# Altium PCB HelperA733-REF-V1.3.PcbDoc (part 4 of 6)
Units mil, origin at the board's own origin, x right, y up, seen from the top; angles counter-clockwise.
Board outline 5905.51 x 4133.86 mil, 2 copper layers (Top, Bottom), stack 12.7 mil thick; 446 components, 341 nets, 1706 pads, 1667 vias.
Unrouted connection lines stored in the file: 1382.
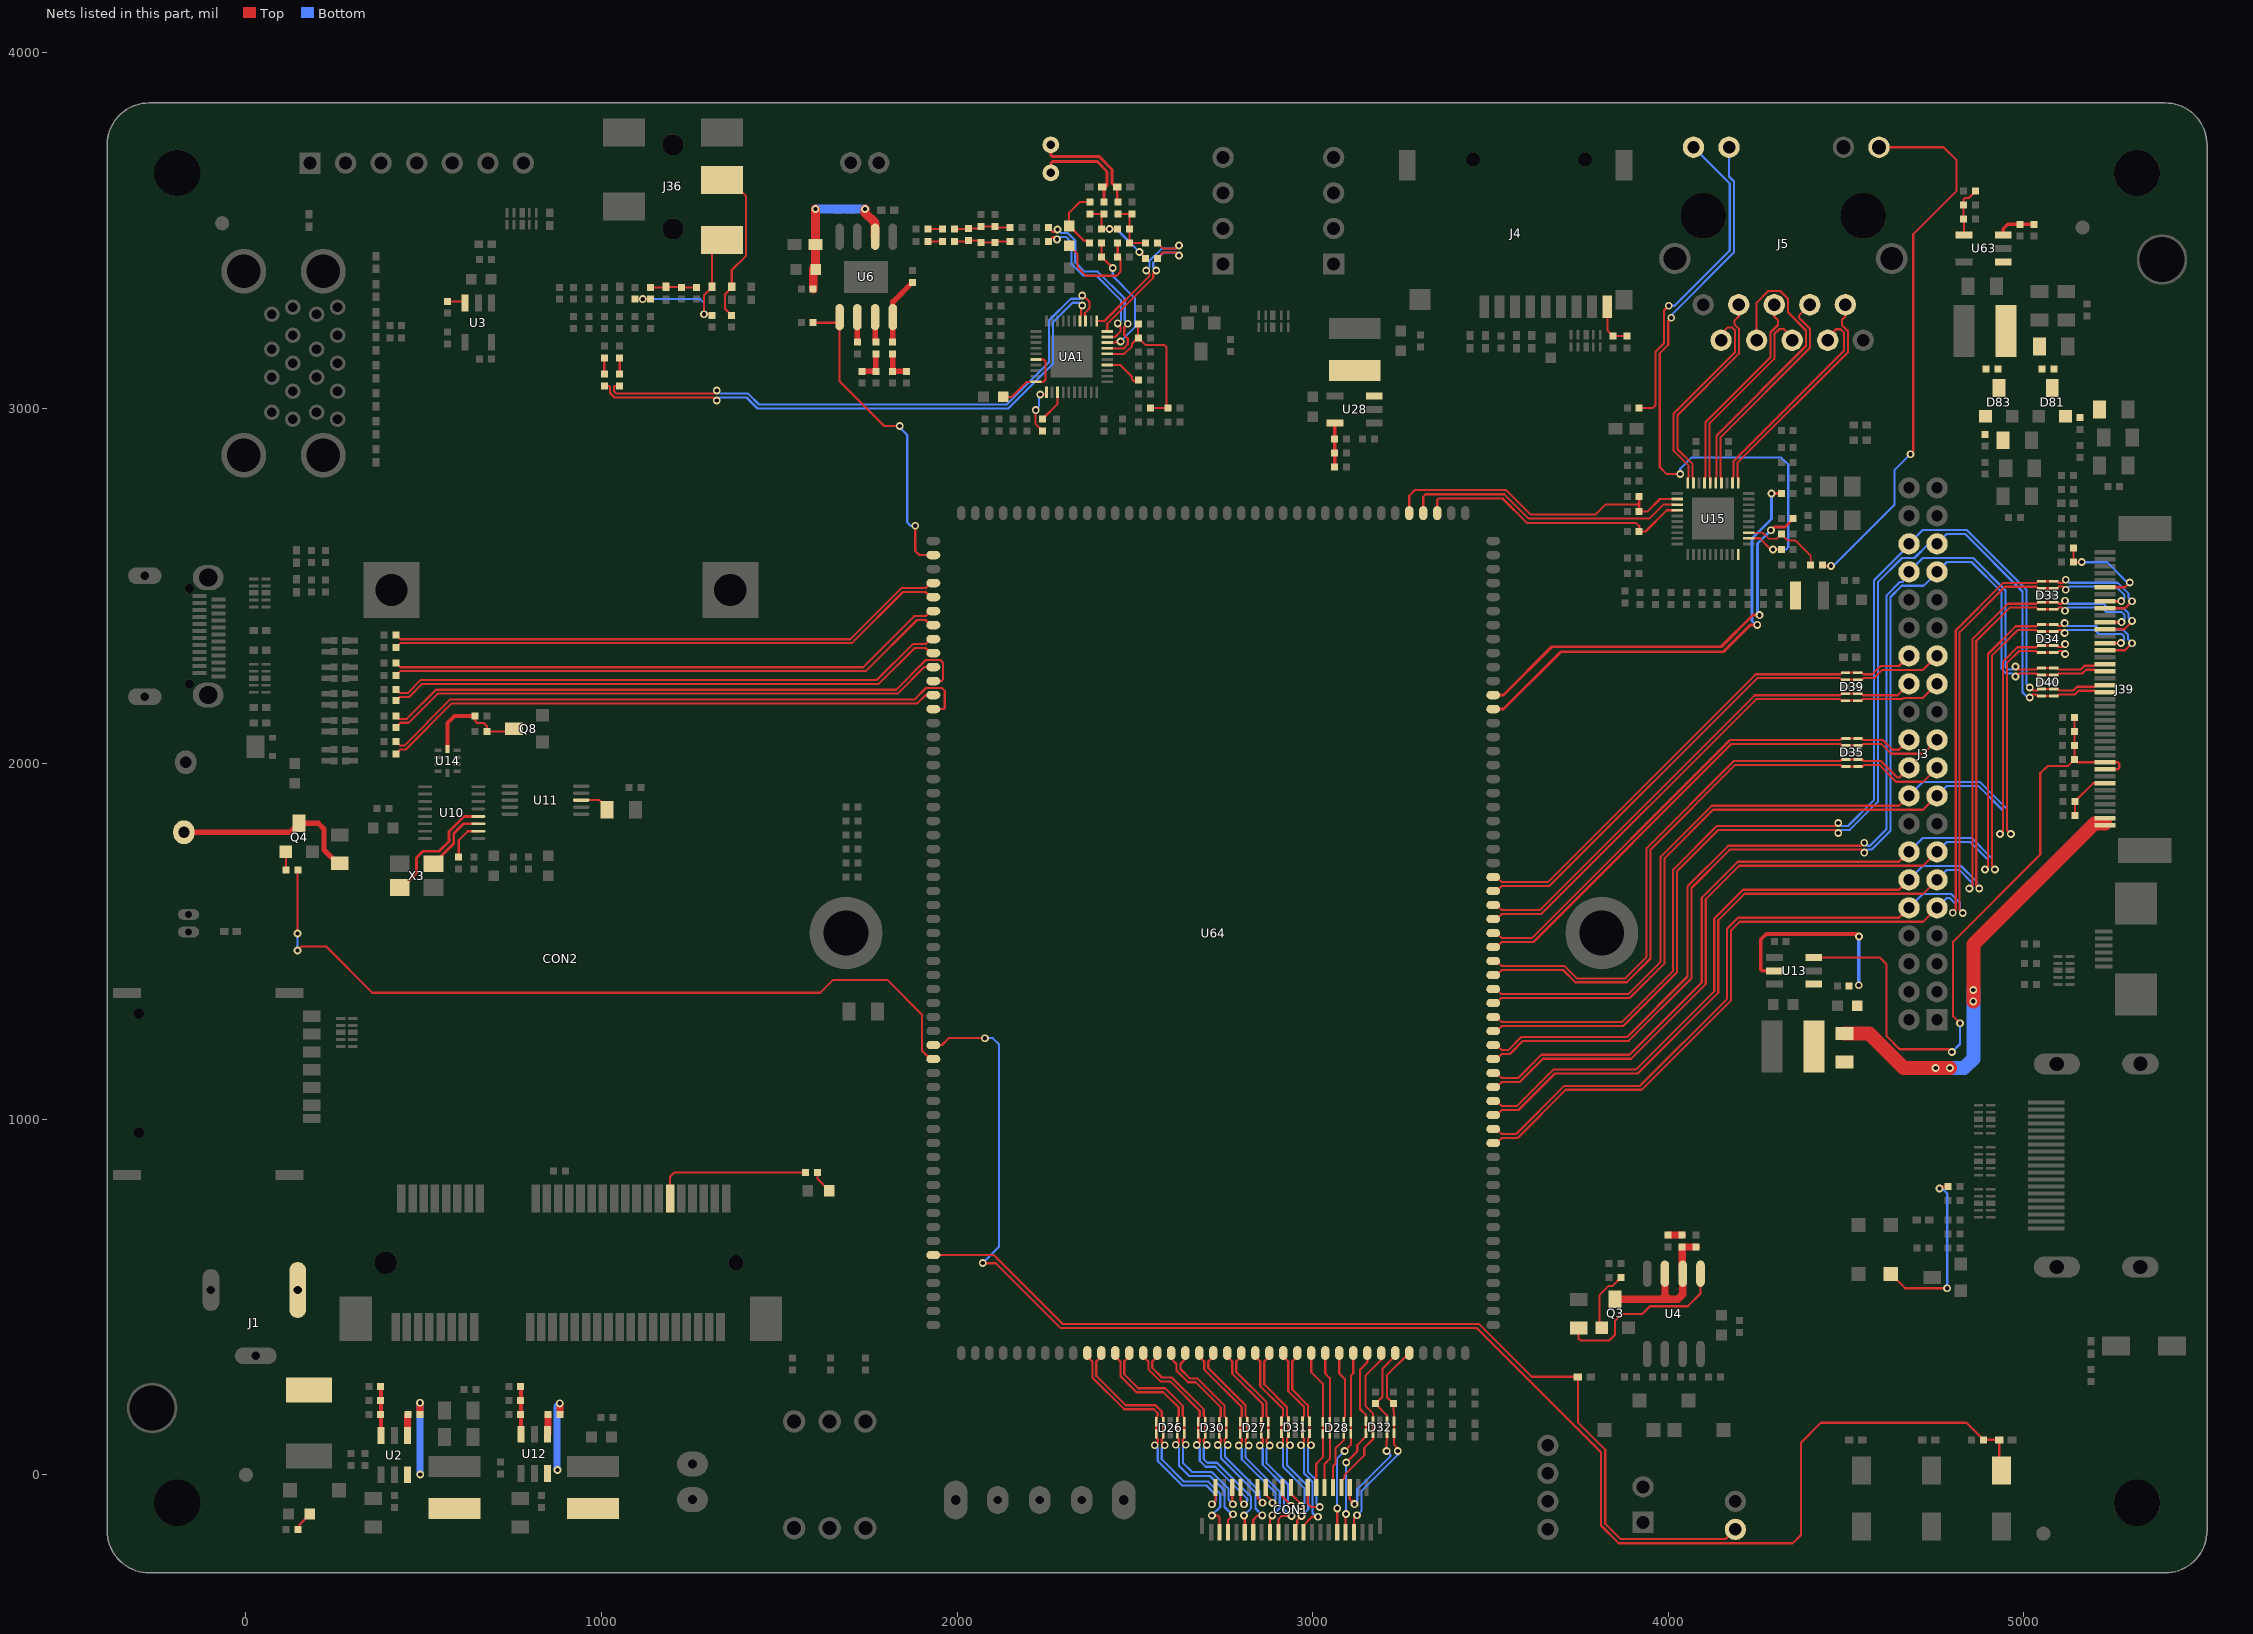
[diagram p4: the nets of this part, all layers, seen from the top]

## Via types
v1: diameter 22, hole 12, Top to Bottom, 1667 vias

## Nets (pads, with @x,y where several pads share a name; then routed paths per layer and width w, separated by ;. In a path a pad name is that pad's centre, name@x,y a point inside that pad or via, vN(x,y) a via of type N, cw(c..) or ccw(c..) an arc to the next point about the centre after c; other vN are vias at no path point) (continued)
LCD_UD: J39.34 R202.2 R204.1 | length 145.2
  Top w6: R202.2@5143.7,1854.33 R204.1@5143.7,1893.7 5194.88,1944.88 J39.34@5228.35,1944.88
LDOIN/RSTN: CA17.1 RA17.1 RA18.2 RA20.1 UA1.36 | length 469.1
  Top w6: UA1.36@2422.44,3152.58 2470.44,3152.58 2492.15,3174.29 2492.15,3181.72 CA17.1@2508.89,3198.45 ; RA18.2@2510.83,3236.22 2508.89,3234.28 CA17.1@2508.89,3198.45 ; RA17.1@2544.29,3000 RA20.1@2593.5,3000 ; RA20.1@2599.6,3000 RA20.1@2593.5,3000 ; CA17.1@2508.89,3198.45 2508.89,3196.85 CA17.1@2510.83,3196.85 2530.51,3177.17 2583.06,3177.17 2588.45,3171.78 2588.45,3005.05 RA20.1@2593.5,3000
LED0_AD0: J5.13 R149.2 U15.32 | length 1780.4
  Top w6: v1(4008.45,3253.89) 4000.2,3245.64 4000.2,3177.93 3976.1,3153.83 3976.1,2834.12 3995.87,2814.35 v1(4033.65,2814.35) ; U15.32@4226.38,2633.86 4257.27,2633.86 4288.76,2602.36 v1(4294.35,2602.36) R149.2@4317.91,2602.36
  Bottom w6: v1(4008.45,3253.89) 4008.45,3261.33 4185.09,3437.97 4185.09,3637.21 4171.05,3651.25 J5.13@4171.05,3733.64 ; v1(4033.65,2814.35) 4033.65,2829.3 4065.08,2860.73 4318.1,2860.73 4337.48,2841.35 4337.48,2608.83 4331.01,2602.36 v1(4294.35,2602.36)
LED1_AD1: R79.2 R150.2 U15.33 | length 237.8
  Top w5: U15.33@4226.38,2649.61 4266.22,2649.61 4283.38,2632.45 4304.69,2632.45 R150.2@4317.91,2645.67 4336.27,2627.31 4358.14,2627.31 4400.59,2584.86 R79.2@4400.59,2559.06
LED+: C91.1 C215.1 D46.2 J39.39 J39.40 U13.5 | length 1865.3
  Top w10: U13.5@4299.21,1417.32 4264.43,1417.32 4260.65,1421.1 4260.65,1505.67 4275.94,1520.96 4529.7,1520.96 v1(4536.6,1514.05)
  Top w39.37: v1(4857.86,1331.56) v1(4857.86,1363.56) 4857.86,1490.84 5199.26,1832.24 J39.40@5228.35,1832.24
  Top w40: D46.2@4496.06,1240.79 4565.31,1240.79 4662.1,1144 v1(4752,1144) v1(4792,1144)
  Bottom w10: v1(4535.8,1376.91) 4535.8,1514.05 v1(4536.6,1514.05)
  Bottom w39.37: v1(4752,1144) v1(4792,1144) 4832,1144 4857.86,1169.86 v1(4857.86,1331.56) v1(4857.86,1363.56)
LED-: J39.31 J39.32 R6.1 R216.1 R217.1 R218.1 U13.3 | length 1934.8
  Top w6: U13.3@4409.45,1454.72 4594.63,1454.72 4614.05,1435.3 4614.05,1233.06 4650.2,1196.91 4789.47,1196.91 v1(4797.59,1188.79) ; v1(4820.54,1269.96) 4801.08,1289.42 4801.08,1499.22 5046.36,1744.5 5046.36,1972.89 5066.43,1992.96 5123.87,1992.96 R218.1@5142.72,2011.81 ; R217.1@5142.72,2129.92 R216.1@5142.72,2090.55 R6.1@5142.72,2051.18 R218.1@5142.72,2011.81 ; J39.32@5228.35,1984.25 5265.03,1984.25 5268.22,1987.44 5268.22,2000.08 5264.36,2003.94 5150.59,2003.94 R218.1@5142.72,2011.81
  Bottom w6: v1(4797.59,1188.79) 4820.54,1211.74 v1(4820.54,1269.96)
LRADC0: D172.2 J42.1 U64.183 | length 2796.7
  Top w6: U64.183@1933.07,618.11 2102.77,618.11 2296.27,424.61 3467.2,424.61 3616.22,275.59 D172.2@3745.78,275.59 ; D172.2@3747.78,275.59 D172.2@3745.78,275.59 ; J42.1@4188.98,-153.54 4162.25,-180.27 3865.31,-180.27 3822.83,-137.8 3822.83,70.91 3745.78,147.96 D172.2@3745.78,275.59
LVDS0-CKN: D40.1 D40.10 J3.34 J39.17 U64.58 | length 3119.8
  Top w6: U64.58@3507.87,1208.66 3517.71,1208.66 3531.9,1194.47 3550.07,1194.47 3586.94,1231.34 3884.28,1231.34 4054.2,1401.26 4054.2,1655.14 4168.31,1769.24 4542.87,1769.24 v1(4551.37,1777.74) ; v1(4976.37,2273.16) 4984.86,2264.66 5034.94,2264.66 5039.28,2269.01 D40.10@5083.97,2269.01 5093.83,2269.01 5098.17,2264.66 5160.16,2264.66 5170.68,2275.18 5197.1,2275.18 5201.44,2279.53 J39.17@5228.35,2279.53
  Bottom w6: v1(4551.37,1777.74) 4559.87,1769.24 4567.21,1769.24 4614.09,1816.12 4614.09,2473.42 4651.88,2511.21 4659.5,2511.21 4677.17,2528.87 J3.34@4677.17,2539.37 4716.17,2578.37 4857.51,2578.37 4948.7,2487.18 4948.7,2271.17 4955.21,2264.66 4967.87,2264.66 v1(4976.37,2273.16)
LVDS0-CKP: D40.2 D40.9 J3.33 J39.18 U64.57 | length 3114.3
  Top w6: U64.57@3507.87,1169.29 3517.71,1169.29 3531.9,1183.47 3554.77,1183.47 3591.63,1220.34 3888.86,1220.34 4065.27,1396.75 4065.27,1650.45 4173.07,1758.24 4542.87,1758.24 v1(4551.37,1749.74) ; v1(4976.37,2245.16) 4984.87,2253.66 5034.91,2253.66 5039.25,2249.32 D40.9@5083.97,2249.32 5094.25,2249.32 5098.59,2253.66 5164.72,2253.66 5175.24,2264.19 5197.61,2264.19 5201.95,2259.84 J39.18@5228.35,2259.84
  Bottom w6: v1(4551.37,1749.74) 4559.87,1758.24 4571.77,1758.24 4625.09,1811.56 4625.09,2468.85 4656.44,2500.2 4718.39,2500.2 4755.91,2537.72 J3.33@4755.91,2539.37 4783.86,2567.32 4852.73,2567.32 4937.67,2482.39 4937.67,2266.6 4950.61,2253.66 4967.87,2253.66 v1(4976.37,2245.16)
LVDS0-D0N: D33.2 D33.9 J3.10 J39.8 U64.52 | length 3154
  Top w6: U64.52@3507.87,972.44 3517.71,972.44 3531.9,958.25 3571.77,958.25 3707.31,1093.79 3920.53,1093.79 4165.77,1339.03 4165.77,1536.22 4196.07,1566.52 4649.19,1566.52 J3.10@4677.17,1594.49 ; v1(4828.16,1580.14) 4819.42,1588.88 4819.42,2369.62 4947.16,2497.36 5035.6,2497.36 5039.55,2493.41 D33.9@5083.97,2493.41 5094.08,2493.41 5098.43,2497.76 5109.58,2497.76 v1(5118.08,2489.26) ; J39.8@5228.35,2456.69 5274.79,2456.69 5274.79,2457.04 v1(5274.22,2457.04)
  Bottom w6: J3.10@4677.17,1594.49 4716.17,1633.49 4795.6,1633.49 4820.03,1609.05 4820.03,1588.27 v1(4828.16,1580.14) ; v1(5118.08,2489.26) 5126.58,2497.76 5259.28,2497.76 5283.63,2473.41 5283.63,2466.45 v1(5274.22,2457.04)
LVDS0-D0P: D33.1 D33.10 J3.9 J39.9 U64.51 | length 3209.1
  Top w6: U64.51@3507.87,933.07 3517.71,933.07 3531.9,947.25 3576.33,947.25 3711.87,1082.79 3925.12,1082.79 4176.89,1334.57 4176.89,1531.6 4200.78,1555.49 4716.91,1555.49 J3.9@4755.91,1594.49 ; v1(4799.94,1580.49) 4808.42,1588.97 4808.42,2374.36 4942.42,2508.36 5035.6,2508.36 5040.34,2513.1 D33.10@5083.97,2513.1 5093.73,2513.1 5098.08,2508.76 5109.58,2508.76 v1(5118.08,2517.26) ; J39.9@5228.35,2437.01 5284.45,2437.01 v1(5304.13,2456.69)
  Bottom w6: J3.9@4755.91,1594.49 4783.91,1622.49 4790.95,1622.49 4809,1604.43 4809,1589.55 v1(4799.94,1580.49) ; v1(5118.08,2517.26) 5126.58,2508.76 5263.88,2508.76 5294.65,2477.99 5294.65,2466.18 v1(5304.13,2456.69)
LVDS0-D1N: D33.5 D33.6 J3.12 J39.11 U64.54 | length 3050.1
  Top w6: U64.54@3507.87,1051.18 3517.71,1051.18 3531.9,1036.99 3574.32,1036.99 3676.83,1139.5 3909.06,1139.5 4129.47,1359.92 4129.47,1564.31 4210.39,1645.23 4649.17,1645.23 J3.12@4677.17,1673.23 ; v1(4874.85,1649.16) 4866.35,1657.66 4866.35,2345.06 4960,2438.7 5035.59,2438.7 5039.93,2434.36 D33.6@5083.97,2434.36 5093.91,2434.36 5098.25,2438.7 5107.34,2438.7 v1(5115.84,2430.2) ; J39.11@5228.35,2397.64 5274.59,2397.64 v1(5274.59,2398)
  Bottom w6: J3.12@4677.17,1673.23 4716.17,1712.23 4823.25,1712.23 4866.35,1669.12 4866.35,1657.66 v1(4874.85,1649.16) ; v1(5115.84,2430.2) 5124.34,2438.7 5219.7,2438.7 5232.36,2426.04 5275.89,2426.04 5283.41,2418.52 5283.41,2406.81 v1(5274.59,2398)
LVDS0-D1P: D33.4 D33.7 J3.11 J39.12 U64.53 | length 3105.7
  Top w6: U64.53@3507.87,1011.81 3517.71,1011.81 3531.9,1025.99 3578.87,1025.99 3681.38,1128.5 3913.78,1128.5 4140.54,1355.26 4140.54,1559.69 4215.08,1634.23 4716.91,1634.23 J3.11@4755.91,1673.23 ; v1(4846.85,1649.16) 4855.35,1657.66 4855.35,2349.99 4955.06,2449.7 5035.17,2449.7 5039.51,2454.04 D33.7@5083.97,2454.04 5094.52,2454.04 5098.87,2449.7 5107.34,2449.7 v1(5115.84,2458.2) ; J39.12@5228.35,2377.95 5282.83,2377.95 5304.13,2399.25 v1(5304.13,2401.57)
  Bottom w6: J3.11@4755.91,1673.23 4783.84,1701.16 4818.69,1701.16 4855.35,1664.5 4855.35,1657.66 v1(4846.85,1649.16) ; v1(5115.84,2458.2) 5124.34,2449.7 5224.26,2449.7 5236.92,2437.04 5280.47,2437.04 5294.46,2423.05 5294.46,2411.25 v1(5304.13,2401.57)
LVDS0-D2N: D34.2 D34.9 J3.14 J39.14 U64.56 | length 2984.1
  Top w6: U64.56@3507.87,1129.92 3517.71,1129.92 3531.9,1115.73 3577.6,1115.73 3643.08,1181.21 3891.16,1181.21 4094.42,1384.48 4094.42,1623.15 4195.24,1723.97 4649.17,1723.97 J3.14@4677.17,1751.97 ; 4910.1,1770.25 4910.1,2303.49 4982.23,2375.62 5035.03,2375.62 5039.28,2371.37 D34.9@5083.97,2371.37 5086.82,2371.37 5094.07,2371.37 5098.42,2375.71 5106.29,2375.71 v1(5114.79,2367.21) ; 4910.1,1770.24 4910.1,1710.71 v1(4918.6,1702.21) ; J39.14@5228.35,2338.58 5275.73,2338.58 v1(5272.89,2339.15)
  Bottom w6: J3.14@4677.17,1751.97 4716.17,1790.97 4853.24,1790.97 4910.1,1734.11 4910.1,1710.71 v1(4918.6,1702.21) ; v1(5114.79,2367.21) 5123.29,2375.71 5199.14,2375.71 5210.43,2364.42 5275.9,2364.42 5281.94,2358.39 5281.94,2348.19 v1(5272.89,2339.15)
LVDS0-D2P: D34.1 D34.10 J3.13 J39.15 U64.55 | length 3037.6
  Top w6: U64.55@3507.87,1090.55 3517.71,1090.55 3531.9,1104.73 3582.16,1104.73 3647.63,1170.21 3895.75,1170.21 4105.5,1379.96 4105.5,1618.63 4199.83,1712.97 4716.91,1712.97 J3.13@4755.91,1751.97 ; v1(4890.6,1702.21) 4899.1,1710.71 4899.1,1765.69 ; 4899.1,1765.69 4899.1,2308.29 4977.43,2386.62 5035.75,2386.62 5040.18,2391.06 D34.10@5083.97,2391.06 5093.16,2391.06 5097.51,2386.71 5106.29,2386.71 v1(5114.79,2395.21) ; J39.15@5228.35,2318.9 5284.45,2318.9 v1(5304.13,2338.58)
  Bottom w6: J3.13@4755.91,1751.97 4783.91,1779.97 4848.5,1779.97 4899.1,1729.37 4899.1,1710.71 v1(4890.6,1702.21) ; v1(5114.79,2395.21) 5123.29,2386.71 5203.7,2386.71 5214.99,2375.42 5280.46,2375.42 5292.95,2362.93 5292.95,2349.77 v1(5304.13,2338.58)
LVDS0-D3N: D40.4 D40.7 J3.36 J39.20 U64.60 | length 3189.5
  Top w6: U64.60@3507.87,1287.4 3517.71,1287.4 3531.9,1273.21 3869.3,1273.21 4013.74,1417.65 4013.74,1701.8 4136.61,1824.67 4469.53,1824.67 v1(4478.03,1833.17) ; v1(5016.94,2214.11) 5025.44,2205.61 5036.12,2205.61 5040.46,2209.95 D40.7@5083.97,2209.95 5094.96,2209.95 5099.3,2205.61 5139.13,2205.61 5149.65,2216.13 5198.6,2216.13 5202.94,2220.47 J39.20@5228.35,2220.47
  Bottom w6: v1(4478.03,1833.17) 4486.53,1824.67 4505.64,1824.67 4578.28,1897.31 4578.28,2515.02 4677.17,2613.9 J3.36@4677.17,2618.11 4716.17,2657.11 4839.06,2657.11 5007.51,2488.66 5007.51,2223.54 v1(5016.94,2214.11)
LVDS0-D3P: D40.5 D40.6 J3.35 J39.21 U64.59 | length 3204.9
  Top w6: U64.59@3507.87,1248.03 3517.71,1248.03 3531.9,1262.21 3873.92,1262.21 4024.78,1413.07 4024.78,1697.21 4141.24,1813.67 4469.53,1813.67 v1(4478.03,1805.17) ; v1(5016.94,2186.11) 5025.44,2194.61 5034.18,2194.61 5038.52,2190.27 D40.6@5083.97,2190.27 5093.75,2190.27 5098.09,2194.61 5143.69,2194.61 5154.21,2205.13 5198.21,2205.13 5202.55,2200.79 J39.21@5228.35,2200.79
  Bottom w6: v1(4478.03,1805.17) 4486.53,1813.67 4510.32,1813.67 4589.41,1892.76 4589.41,2510.53 4657.29,2578.41 4692.69,2578.41 4732.39,2618.11 J3.35@4755.91,2618.11 4783.91,2646.11 4834.5,2646.11 4996.38,2484.24 4996.38,2200.67 5010.94,2186.11 v1(5016.94,2186.11)
LVDS1-CKN: D39.2 D39.9 J3.26 U64.68 | length 1442.3
  Top w6: U64.68@3507.87,1602.36 3517.71,1602.36 3531.9,1588.18 3638.51,1588.18 4242.85,2192.51 4482.88,2192.51 4487.22,2196.86 D39.2@4532.79,2196.86 4543.15,2196.86 4547.49,2192.51 4645.27,2192.51 J3.26@4677.17,2224.41
LVDS1-CKP: D39.1 D39.10 J3.25 U64.67 | length 1525.6
  Top w6: U64.67@3507.87,1562.99 3517.71,1562.99 3531.9,1577.18 3643.07,1577.18 4247.41,2181.51 4482.44,2181.51 4486.78,2177.17 D39.1@4532.79,2177.17 4542.9,2177.17 4547.24,2181.51 4657.85,2181.51 4661.01,2184.67 4716.17,2184.67 J3.25@4755.91,2224.41
LVDS1-D0N: D34.5 D34.6 J3.18 U64.62 | length 2647.7
  Top w6: U64.62@3507.87,1366.14 3515.75,1366.14 3529.93,1351.95 3887.48,1351.95 3978.75,1443.22 3978.75,1738.5 4121.92,1881.67 4649.38,1881.67 J3.18@4677.17,1909.45 ; v1(4963.57,1802.25) 4952.33,1813.48 4952.33,2282.33 4986.47,2316.47 5034.1,2316.47 5038.25,2312.32 D34.6@5083.97,2312.32 5085.75,2312.32 5093.74,2312.32 5098.09,2316.66 5107.68,2316.66 v1(5116.18,2308.16)
  Bottom w6: J3.18@4677.17,1909.45 4716.17,1948.45 4715.79,1948.83 4876.24,1948.83 4952.33,1872.74 4952.33,1815.18 4963.57,1803.94 v1(4963.57,1802.25)
LVDS1-D0P: D34.4 D34.7 J3.17 U64.61 | length 2644.6
  Top w6: U64.61@3507.87,1326.77 3515.75,1326.77 3529.93,1340.95 3892.04,1340.95 3989.75,1438.67 3989.75,1733.94 4126.02,1870.21 4716.67,1870.21 J3.17@4755.91,1909.45 ; v1(4932.81,1802.18) 4941.33,1810.7 4941.33,2286.89 4981.91,2327.47 5035.43,2327.47 5039.96,2332 D34.7@5083.97,2332 5086.01,2332 5092.99,2332 5097.33,2327.66 5107.68,2327.66 v1(5116.18,2336.16)
  Bottom w6: J3.17@4755.91,1909.45 4783.91,1937.45 4871.94,1937.45 4941.33,1868.06 4941.33,1810.7 v1(4932.81,1802.18)
LVDS1-D1N: D35.2 D35.9 J3.20 U64.64 | length 1656
  Top w6: U64.64@3507.87,1444.88 3517.71,1444.88 3531.9,1430.69 3708.52,1430.69 3742.95,1396.27 3878.94,1396.27 3939.15,1456.49 3939.15,1762.54 4184.08,2007.47 4483.45,2007.47 4487.79,2011.82 D35.9@4499.69,2011.82 D35.2@4533.77,2011.82 4545.36,2011.82 4549.7,2007.47 4597.92,2007.47 4644.43,1960.96 4649.94,1960.96 J3.20@4677.17,1988.19
LVDS1-D1P: D35.1 D35.10 J3.19 U64.63 | length 1739.9
  Top w6: U64.63@3507.87,1405.51 3517.71,1405.51 3531.9,1419.69 3703.97,1419.69 3738.39,1385.27 3883.51,1385.27 3950.17,1451.93 3950.17,1757.95 4188.69,1996.47 4484.47,1996.47 4488.81,1992.13 D35.10@4499.69,1992.13 D35.1@4533.77,1992.13 4546.43,1992.13 4550.77,1996.47 4593.36,1996.47 4640.64,1949.19 4716.91,1949.19 J3.19@4755.91,1988.19
LVDS1-D2N: D35.5 D35.6 J3.22 U64.66 | length 1432.5
  Top w6: U64.66@3507.87,1523.62 3517.71,1523.62 3531.9,1509.43 3616.39,1509.43 4173.48,2066.53 4484.11,2066.53 4488.45,2070.87 D35.6@4499.69,2070.87 D35.5@4533.77,2070.87 4544.33,2070.87 4548.67,2066.53 4603.69,2066.53 4631.28,2038.94 4649.18,2038.94 J3.22@4677.17,2066.93
LVDS1-D2P: D35.4 D35.7 J3.21 U64.65 | length 1515.8
  Top w6: U64.65@3507.87,1484.25 3517.71,1484.25 3531.9,1498.44 3620.95,1498.44 4178.04,2055.53 4483.55,2055.53 4487.89,2051.19 D35.7@4499.69,2051.19 D35.4@4533.77,2051.19 4544.19,2051.19 4548.53,2055.53 4599.14,2055.53 4626.73,2027.93 4716.91,2027.93 J3.21@4755.91,2066.93
LVDS1-D3N: D39.5 D39.6 J3.28 U64.70 | length 1442.3
  Top w6: U64.70@3507.87,1681.1 3517.71,1681.1 3531.9,1666.92 3661.05,1666.92 4245.7,2251.57 4484.01,2251.57 4488.35,2255.91 4544.7,2255.91 4549.04,2251.57 4573.96,2251.57 4597.17,2274.78 4648.8,2274.78 J3.28@4677.17,2303.15
LVDS1-D3P: D39.4 D39.7 J3.27 U64.69 | length 1525.6
  Top w6: U64.69@3507.87,1641.73 3517.71,1641.73 3531.9,1655.92 3665.63,1655.92 4250.28,2240.57 4482.83,2240.57 4487.17,2236.23 4545.08,2236.23 4549.42,2240.57 4578.51,2240.57 4601.73,2263.78 4716.54,2263.78 J3.27@4755.91,2303.15
MBIAS: CA5.2 RA5.2 UA1.38 | length 371.1
  Top w6: RA5.2@2406.5,3464.57 CA5.2@2406.5,3425.2 2406.68,3425.2 2426.01,3405.86 2426.21,3405.86 2427.93,3405.35 v1(2437.81,3393.66) ; UA1.38@2422.44,3184.08 2451.91,3184.04 2451.91,3184.21 v1(2459.96,3187.57)
  Bottom w6: v1(2437.81,3393.66) 2437.81,3371.39 2500.05,3309.15 2500.05,3227.67 v1(2459.96,3187.57)
MCSI0-MCLK: CON1.26 D28.1 D28.10 U64.26 | length 399.1
  Top w6: U64.26@2996.06,342.52 2996.06,288.48 3028.57,255.97 D28.1@3028.57,115.28 3028.57,49.78 3009.97,31.18 CON1.26@3009.97,-35.4
MCSI2-MCLK: CON1.28 D28.2 D28.9 U64.27 | length 389.3
  Top w6: CON1.28@3033.59,-35.4 3033.59,30.5 3048.26,45.17 D28.2@3048.26,115.28 3048.26,271.99 3035.43,284.82 U64.27@3035.43,342.52
MCSI-RST-F: CON1.31 D28.5 D28.6 U64.29 | length 522.7
  Top w6: v1(3068.92,-94.38) 3069.02,-94.49 CON1.31@3069.02,-161.38 ; v1(3089.92,67.15) 3107.31,84.54 D28.5@3107.31,115.28 3107.31,278.58 3114.17,285.44 U64.29@3114.17,342.52
  Bottom w6: v1(3068.92,-94.38) 3068.92,46.15 v1(3089.92,67.15)
MCSI-RST-R: CON1.32 D32.4 D32.7 U64.31 | length 441.6
  Top w6: CON1.32@3080.83,-35.4 3080.83,-17.68 3089.2,-9.31 3089.2,-0.87 3145.04,54.97 3145.04,75.75 3164,94.71 3164.72,94.71 3169.29,99.27 D32.7@3169.29,116.82 D32.4@3169.29,150.9 3169.29,172.82 3148.98,193.13 3148.98,279.75 3192.91,323.68 U64.31@3192.91,342.52
MCSI-SCK-TWI2: CON1.34 D32.2 D32.9 R8.2 U64.32 | length 572.9
  Top w6: CON1.34@3104.45,-35.4 3104.45,-69.5 3108.8,-73.85 3112.14,-72.8 v1(3117.48,-82.46) v1@3110.67,-74.27 ; v1(3208.03,67.15) 3208.03,94.08 3208.66,94.71 D32.9@3208.66,116.82 D32.2@3208.66,150.9 3208.66,167.9 R8.2@3176.54,200.02 3196.64,220.13 3196.64,299.01 3232.28,334.65 U64.32@3232.28,342.52
  Bottom w6: v1(3117.48,-82.46) 3125.46,-74.48 3125.46,-40.49 3218.1,52.15 3218.1,57.08 v1(3208.03,67.15)
MCSI-SDA-TWI2: CON1.35 D32.1 D32.10 R9.2 U64.33 | length 593.8
  Top w6: CON1.35@3116.26,-161.38 3116.26,-122.48 v1(3124.88,-113.86) ; v1(3239.53,67.15) 3239.53,75.02 3228.35,86.2 D32.10@3228.35,116.82 D32.1@3228.35,150.9 3228.35,176.77 3227.72,177.4 R9.2@3227.72,200.02 3208.75,218.99 3208.75,279.61 U64.33@3271.65,342.52
  Bottom w6: v1(3124.88,-113.86) 3137.67,-101.07 3137.67,-45.28 3239.53,56.58 v1(3239.53,67.15)
MCSI-STBY-F: CON1.30 D28.4 D28.7 U64.28 | length 398.9
  Top w6: CON1.30@3057.21,-35.4 3057.21,23.61 3063.9,30.3 3063.9,73.92 3087.63,97.65 D28.4@3087.63,115.28 3087.63,160.39 3091.37,164.13 3091.37,268.23 3074.8,284.8 U64.28@3074.8,342.52
MCSI-STBY-R: CON1.33 D32.5 D32.6 U64.30 | length 543.6
  Top w6: CON1.33@3092.64,-161.38 3092.64,-111.23 v1(3093.86,-110.02) ; v1(3094.7,34.74) 3125.35,65.39 3125.35,83.41 3149.61,107.66 D32.6@3149.61,116.82 D32.5@3149.61,150.9 3149.61,168.81 3133.23,185.19 3133.23,295.5 3153.54,315.81 U64.30@3153.54,342.52
  Bottom w6: v1(3093.86,-110.02) 3093.86,31.72 3092.77,32.81 v1(3094.7,34.74)
MCSIA-CKN: CON1.14 D27.1 D27.10 U64.18 | length 580.3
  Top w6: U64.18@2681.1,342.52 2681.1,332.68 2695.29,318.49 2695.29,295.92 2800.63,190.58 2800.63,164.3 2796.28,159.96 D27.1@2796.28,115.28 2796.28,104.59 2800.61,100.27 2800.61,91 v1(2792.13,82.52) ; CON1.14@2868.23,-35.4 2868.23,-56.11 2889.09,-76.98 2890.69,-78.58 v1(2887.24,-78.83)
  Bottom w6: v1(2792.13,82.52) 2800.63,74.02 2800.63,43.84 2895.73,-51.27 2895.73,-70.34 v1(2887.24,-78.83)
MCSIA-CKP: CON1.15 D27.2 D27.9 U64.19 | length 619.4
  Top w6: U64.19@2720.47,342.52 2720.47,332.68 2706.29,318.49 2706.29,300.48 2811.63,195.14 2811.63,165.04 2815.97,160.69 D27.2@2815.97,115.28 2815.97,104.65 2811.63,100.31 2811.63,91.02 v1(2820.13,82.52) ; CON1.15@2880.04,-161.38 2880.04,-125.28 2888.86,-116.46 2890.2,-115.12 v1(2886.43,-114.02)
  Bottom w6: v1(2820.13,82.52) 2811.63,74.02 2811.63,48.4 2907.31,-47.28 2907.31,-93.14 v1(2886.43,-114.02)
MCSIA-D0N: CON1.11 D30.4 D30.7 U64.16 | length 651.1
  Top w6: U64.16@2602.36,342.52 2602.34,326.55 2617.17,311.72 2617.17,292.83 2649.73,260.27 2670.88,260.27 2741.57,189.58 2741.57,164.44 2737.23,160.1 D30.4@2737.23,115.28 2737.23,104.97 2741.57,100.63 2741.57,92.06 v1(2733.07,83.56) ; CON1.11@2832.8,-161.38 2832.8,-126.9 2845.53,-114.17 2857.65,-114.17 2857.65,-114.1 v1(2858.34,-114.1)
  Bottom w6: v1(2733.07,83.56) 2742.21,74.42 2742.21,46.78 2839.14,-50.15 2839.14,-94.9 v1(2858.34,-114.1)
MCSIA-D0P: CON1.12 D30.5 D30.6 U64.17 | length 595.2
  Top w6: U64.17@2641.73,342.52 2641.12,341.91 2641.12,324.74 2628.22,311.84 2628.22,297.39 2654.34,271.27 2675.44,271.27 2752.57,194.13 2752.57,164.55 2756.91,160.21 D30.5@2756.91,115.28 2756.91,103.76 2752.57,99.42 2752.57,92.06 v1(2761.07,83.56) ; CON1.12@2844.61,-35.4 2844.61,-63.76 2859.17,-78.32 v1(2859.17,-78.42)
  Bottom w6: v1(2761.07,83.56) 2753.22,75.71 2753.22,51.36 2850.24,-45.66 2850.24,-65.87 2860.98,-76.61 v1(2859.17,-78.42)
MCSIA-D1N: CON1.8 D30.1 D30.10 U64.14 | length 643.7
  Top w6: U64.14@2523.62,342.52 2523.62,332.68 2537.81,318.49 2537.81,296.71 2571.69,262.83 2599.11,262.83 2682.52,179.42 2682.52,164.44 2678.17,160.09 D30.1@2678.17,115.28 2678.17,104.53 2682.48,100.23 2682.48,92.38 v1(2674.02,83.92) ; CON1.8@2797.37,-35.4 2797.37,-72.96 v1(2807.09,-82.68)
  Bottom w6: v1(2674.02,83.92) 2682.52,75.42 2682.52,39.65 2699.33,22.83 2726.24,22.83 2815.98,-66.91 2815.98,-73.78 v1(2807.09,-82.68)
MCSIA-D1P: CON1.9 D30.2 D30.9 U64.15 | length 676.7
  Top w6: U64.15@2562.99,342.52 2562.99,332.68 2548.81,318.49 2548.81,301.27 2576.24,273.84 2603.68,273.84 2693.52,184 2693.52,165.26 2697.86,160.92 D30.2@2697.86,115.28 2697.86,104.1 2693.52,99.75 2693.52,92.42 v1(2702.02,83.92) ; v1(2807.09,-114.17) 2809.18,-116.27 CON1.9@2809.18,-161.38
  Bottom w6: v1(2702.02,83.92) 2693.52,75.42 2693.52,44.2 2703.89,33.83 2730.81,33.83 2827.09,-62.44 2827.09,-94.17 v1(2807.09,-114.17)
MCSIA-D2N: CON1.5 D26.4 D26.7 U64.12 | length 740.5
  Top w6: U64.12@2444.88,342.52 2444.88,332.68 2459.07,318.49 2459.07,277.73 2504.48,232.31 2580.25,232.31 2623.46,189.1 2623.46,165.19 2619.12,160.85 2619.12,104.42 2623.46,100.08 2623.46,93.02 v1(2614.96,84.52) ; CON1.5@2761.93,-161.38 2761.93,-127.83 2775.59,-114.17 2776.12,-111.19 v1(2776.14,-110.73)
  Bottom w6: v1(2614.96,84.52) 2623.8,75.69 2623.8,25.99 2653.04,-3.25 2711.43,-3.25 2752.16,-43.98 2752.16,-90.74 2774.36,-112.95 2776.12,-111.19 v1(2776.14,-110.73)
MCSIA-D2P: CON1.6 D26.5 D26.6 U64.13 | length 692.4
  Top w6: U64.13@2484.25,342.52 2484.25,332.68 2470.07,318.49 2470.07,282.4 2509.15,243.31 2584.97,243.31 2634.46,193.82 2634.46,165.27 2638.8,160.93 2638.8,103.99 2634.46,99.65 2634.46,93.02 v1(2642.96,84.52) ; CON1.6@2773.75,-35.4 2773.75,-80.84 v1(2775.59,-82.68)
  Bottom w6: v1(2642.96,84.52) 2634.86,76.42 2634.86,34.17 2661.19,7.84 2715.92,7.84 2763.16,-39.4 2763.16,-70.24 v1(2775.59,-82.68)
MCSIA-D3N: CON1.2 D26.1 D26.10 U64.10 | length 732.5
  Top w6: U64.10@2366.14,342.52 2366.14,332.68 2380.33,318.49 2380.33,273.88 2469.69,184.51 2553.26,184.51 2564.41,173.36 2564.41,164.9 2560.06,160.55 D26.1@2560.06,115.28 2560.06,104.93 2564.4,100.59 2564.4,91.71 v1(2555.91,83.22) ; v1(2716.54,-82.68) 2726.5,-76.9 CON1.2@2726.5,-35.4
  Bottom w6: v1(2555.91,83.22) 2564.41,74.72 2564.41,38.94 2633.55,-30.2 2701.45,-30.2 2728.35,-57.09 2728.35,-70.87 v1(2716.54,-82.68)
MCSIA-D3P: CON1.3 D26.2 D26.9 U64.11 | length 781.8
  Top w6: U64.11@2405.51,342.52 2405.51,332.68 2391.33,318.49 2391.33,278.43 2474.23,195.53 2557.81,195.53 2575.41,177.93 2575.41,164.66 2579.75,160.31 D26.2@2579.75,115.28 2579.75,103.94 2575.41,99.59 2575.41,91.72 v1(2583.91,83.22) ; v1(2716.54,-114.17) 2732.28,-114.17 2738.31,-120.2 CON1.3@2738.31,-161.38
  Bottom w6: v1(2583.91,83.22) 2575.41,74.72 2575.41,43.5 2638.1,-19.19 2706.21,-19.19 2740.16,-53.13 2740.16,-90.55 v1(2716.54,-114.17)
MCSIC-CKN: CON1.23 D31.4 D31.7 U64.24 | length 586.3
  Top w6: U64.24@2917.32,342.52 2917.32,332.68 2931.51,318.49 2931.51,274.87 2931.51,235.42 2975.51,191.42 2975.51,165.87 2971.17,161.53 D31.7@2971.17,150.25 D31.4@2971.17,116.17 2971.17,105.17 2975.51,100.83 2975.51,91.79 v1(2967.01,83.29) ; CON1.23@2974.53,-161.38 2974.53,-141.4 2998.02,-117.92 v1(3014.88,-117.92)
  Bottom w6: v1(2967.01,83.29) 2975.51,74.79 2975.51,4.23 2999.74,-20.01 2999.74,-107.27 3012.8,-120.33 v1(3014.88,-117.92)
MCSIC-CKP: CON1.24 D31.5 D31.6 U64.25 | length 577.5
  Top w6: U64.25@2956.69,342.52 2956.69,332.68 2942.51,318.49 2942.51,270.32 2942.51,239.97 2986.51,195.97 2986.51,165.05 2990.85,160.71 D31.6@2990.85,150.25 D31.5@2990.85,116.17 2990.85,104.97 2986.51,100.63 2986.51,91.79 v1(2995.01,83.29) ; CON1.24@2986.34,-35.4 2986.34,-80.34 2996.42,-90.41 v1(3020.14,-90.41)
  Bottom w6: v1(2995.01,83.29) 2986.51,74.79 2986.51,8.81 3010.74,-15.43 3010.74,-81.13 3020.09,-90.47 v1@3024.98,-95.36 ; v1(3020.14,-90.41) v1@3024.74,-86.58
MCSIC-D0N: CON1.20 D31.1 D31.10 U64.22 | length 565.4
  Top w6: U64.22@2838.58,342.52 2838.58,332.68 2852.77,318.49 2852.77,249.52 2916.45,185.84 2916.45,165.65 2912.11,161.3 D31.10@2912.11,150.25 D31.1@2912.11,116.17 2912.11,107.06 2916.42,102.75 2916.42,91.59 v1(2907.95,83.13) ; CON1.20@2939.1,-35.4 2939.1,-54.03 2967.64,-82.57 v1(2967.64,-87.45)
  Bottom w6: v1(2907.95,83.13) 2916.45,74.63 2916.45,22.67 2976.68,-37.56 2976.68,-78.41 v1(2967.64,-87.45)
MCSIC-D0P: CON1.21 D31.2 D31.9 U64.23 | length 587
  Top w6: U64.23@2877.95,342.52 2877.95,332.68 2863.77,318.49 2863.77,254.24 2927.45,190.56 2927.45,166.52 2931.8,162.17 D31.9@2931.8,150.25 D31.2@2931.8,116.17 2931.8,105.87 2927.45,101.52 2927.45,91.63 v1(2935.95,83.13) ; CON1.21@2950.91,-161.38 2950.91,-143.66 2956.72,-137.86 2956.72,-128.13 v1(2968.83,-116.02)
  Bottom w6: v1(2935.95,83.13) 2927.45,74.63 2927.45,27.45 2987.73,-32.84 2987.73,-97.12 v1(2968.83,-116.02)
MCSIC-D1N: CON1.17 D27.4 D27.7 U64.20 | length 622.7
  Top w6: U64.20@2759.84,342.52 2759.84,332.68 2774.03,318.49 2774.03,284.69 2859.68,199.04 2859.68,164.83 2855.34,160.49 D27.4@2855.34,115.28 2855.34,104.9 2859.68,100.56 2859.68,91.21 v1(2851.18,82.71) ; CON1.17@2903.67,-161.38 2903.67,-124.85 2913.09,-115.44 2939.09,-115.44 v1(2940.73,-116.09)
  Bottom w6: v1(2851.18,82.71) 2859.68,74.2 2859.68,28.14 2919.43,-31.61 2919.43,-96.98 2936.46,-114.01 2939.09,-115.44 v1(2940.73,-116.09)
MCSIC-D1P: CON1.18 D27.5 D27.6 U64.21 | length 571.1
  Top w6: U64.21@2799.21,342.52 2799.21,332.68 2785.03,318.49 2785.03,289.25 2870.68,203.59 2870.68,164.85 2875.02,160.51 D27.5@2875.02,115.28 2875.02,103.89 2870.68,99.55 2870.68,91.21 v1(2879.18,82.71) ; CON1.18@2915.48,-35.4 2915.48,-62.51 2939.43,-86.46 v1(2939.43,-86.77)
  Bottom w6: v1(2879.18,82.71) 2870.68,74.2 2870.68,32.69 2930.49,-27.12 2930.49,-77.83 v1(2939.43,-86.77)
MDI0+: J5.2 U15.1 | length 642.5
  Top w6: U15.1@4196.85,2789.37 4196.85,2803.21 4194.48,2805.58 4194.48,2845.99 4505.65,3157.17 4505.65,3216.26 4488.37,3233.54 4488.37,3247.88 4498.22,3257.72 J5.2@4498.22,3290.72
MDI0-: J5.3 U15.2 | length 619.7
  Top w6: U15.2@4181.1,2789.37 4181.1,2804.12 4183.48,2806.49 4183.48,2850.64 4494.65,3161.82 4494.65,3211.7 4484.67,3221.68 4471.94,3221.68 4453.46,3203.2 4453.46,3195.57 J5.3@4448.61,3190.72
MDI1+: J5.4 U15.4 | length 631.5
  Top w6: U15.4@4149.61,2789.37 4149.61,2803.98 4147.23,2806.35 4147.23,2918.38 4398.61,3169.76 4398.61,3222.89 4368.21,3253.3 4368.21,3260.71 J5.4@4398.22,3290.72
MDI1-: J5.7 U15.5 | length 861
  Top w6: U15.5@4133.86,2789.37 4133.86,2804.26 4136.23,2806.63 4136.23,2923.1 4387.61,3174.48 4387.61,3218.34 4337.22,3268.73 4337.22,3306.88 4314.37,3329.72 4282.06,3329.72 4248.61,3296.27 J5.7@4248.61,3190.72
MDI2+: J5.5 U15.6 | length 569.3
  Top w6: U15.6@4118.11,2789.37 4118.11,2803.12 4115.74,2805.49 4115.74,2955.9 4298.61,3138.77 4298.61,3208.14 4312.97,3222.5 4324.85,3222.5 4344.82,3202.54 4344.82,3194.51 J5.5@4348.61,3190.72
MDI2-: J5.6 U15.7 | length 591
  Top w6: U15.7@4102.36,2789.37 4102.36,2804.49 4104.74,2806.86 4104.74,2960.51 4287.61,3143.38 4287.61,3212.7 4308.56,3233.65 4308.56,3247.38 4298.22,3257.72 J5.6@4298.22,3290.72
MDI3+: J5.8 U15.9 | length 601.5
  Top w6: U15.9@4070.87,2789.37 4070.87,2802.9 4068.49,2805.27 4068.49,2842.27 4026.12,2884.64 4026.12,2979.96 4198.61,3152.45 4198.61,3223.3 4186.09,3235.83 4186.09,3245.59 4198.22,3257.72 J5.8@4198.22,3290.72
MDI3-: J5.9 U15.10 | length 586.9
  Top w6: U15.10@4055.12,2789.37 4055.12,2803.41 4057.49,2805.78 4057.49,2837.71 4015.12,2880.09 4015.12,2984.55 4187.61,3157.04 4187.61,3218.75 4179.96,3226.39 4166.22,3226.39 4148.61,3208.78 J5.9@4148.61,3190.72
MIC1N-MIC: DA2.2 MIC1.2 RA101.1 | length 319
  Top w8: MIC1.2@2263.78,3740.16 2263.78,3711.04 2267.7,3707.12 2399.68,3707.12 2435.98,3670.82 2435.98,3631.49 2445.42,3622.05 DA2.2@2450.5,3622.05 2450.5,3581.98 RA101.1@2452.76,3579.72
MIC1P-MIC: DA1.2 MIC1.1 RA100.1 | length 303
  Top w8: MIC1.1@2263.78,3661.42 2263.78,3688.69 2268.08,3692.99 2394.01,3692.99 2421.96,3665.04 2421.96,3624.61 2414.76,3617.41 2410.12,3622.05 DA1.2@2407.76,3622.05 2413.39,3616.43 RA100.1@2413.39,3579.72
MIC2N/MIC3N: RA80.2 UA1.39 | length 461.2
  Top w6: RA80.2@2256.89,3468.5 2269.5,3481.11 2274.56,3481.11 v1(2281.13,3474.54) ; UA1.39@2422.44,3199.83 2443.91,3199.83 2459.14,3215.06 2459.14,3231.17 v1(2452,3238.32)
  Bottom w6: v1(2281.13,3474.54) 2287.85,3481.27 2306.58,3481.27 2321.36,3466.49 2321.36,3406.2 2354.86,3372.7 2391.31,3372.7 2460.51,3303.5 2460.51,3246.83 v1(2452,3238.32)
MIC2P/MIC3P: RA79.2 UA1.37 | length 542.9
  Top w6: RA79.2@2256.89,3507.87 2269.9,3494.86 2274.7,3494.86 v1(2282.38,3502.54) ; UA1.37@2422.44,3168.33 2422.44,3167.57 2468.24,3167.57 2479.96,3179.29 2479.96,3195.87 2470.17,3205.66 2470.17,3227.51 v1(2480.03,3237.37)
  Bottom w6: v1(2282.38,3502.54) 2292.62,3492.3 2311.51,3492.3 2332.42,3471.39 2332.42,3410.7 2359.39,3383.72 2395.92,3383.72 2471.51,3308.13 2471.51,3245.89 v1(2480.03,3237.37)
MICIN1N: CA9.1 UA1.1 | length 420.7
  Top w6: UA1.1@2392.91,3245.1 2414.66,3245.1 2540.74,3371.19 2540.74,3378.14 v1(2532.24,3386.64) ; CA9.1@2563.98,3464.57 2580.13,3448.41 2615.42,3448.41 v1(2623.92,3456.91)
  Bottom w6: v1(2532.24,3386.64) 2540.74,3395.14 2540.74,3413.52 2575.63,3448.41 2615.42,3448.41 v1(2623.92,3456.91)
MICIN1P: CA6.1 UA1.40 | length 411.6
  Top w6: UA1.40@2422.44,3215.58 2422.44,3237.33 2551.74,3366.63 2551.74,3378.14 v1(2560.24,3386.64) ; CA6.1@2563.98,3421.26 2580.13,3437.41 2615.42,3437.41 v1(2623.92,3428.91)
  Bottom w6: v1(2560.24,3386.64) 2551.74,3395.14 2551.74,3408.87 2580.29,3437.41 2615.42,3437.41 v1(2623.92,3428.91)
MICIN4N: C182.1 UA1.4 | length 1628.1
  Top w6: C182.1@1007.87,3062.01 1021.28,3062.01 1024.03,3059.26 1024.03,3042.31 1036.62,3029.72 1315.37,3029.72 v1(1323.87,3021.22) ; UA1.4@2345.66,3245.1 2345.66,3257.61 2348.04,3259.99 2348.04,3284.2 v1(2352.05,3288.2)
  Bottom w6: v1(1323.87,3021.22) 1332.37,3029.72 1407.57,3029.72 1438.57,2998.72 2143.62,2998.72 2269.67,3124.78 2269.67,3241.51 2324.46,3296.3 2343.95,3296.3 v1(2352.05,3288.2)
MICIN4P: C181.1 UA1.3 | length 1671.1
  Top w6: C181.1@1051.18,3062.01 1037.88,3062.01 1035.03,3059.16 1035.03,3046.99 1041.3,3040.72 1315.37,3040.72 v1(1323.87,3049.22) ; v1(2351.89,3316.57) 2353.43,3316.22 2354.92,3316.43 2354.87,3316.8 2372.08,3299.59 2372.08,3279.9 2359.04,3266.86 2359.04,3260.85 2361.41,3258.48 UA1.3@2361.41,3245.1
  Bottom w6: v1(1323.87,3049.22) 1332.37,3040.72 1412.21,3040.72 1443.01,3009.92 2139.23,3009.92 2258.65,3129.35 2258.65,3246.12 2319.88,3307.35 2346.17,3307.35 2355.77,3316.96 2354.02,3318.71 2351.61,3321.12 2353.47,3318.94 2352.93,3318.47 2353.43,3317.89 2354.25,3316.92 2353.43,3316.22 v1(2351.89,3316.57)
N39839: J4.9 R10.2 R294.2 | length 128.6
  Top w6: J4.9@3828.74,3285.43 3828.74,3218.68 R294.2@3844.6,3202.82 R10.2@3883.97,3202.82
N638326: J5.14 R81.1 | length 913.3
  Top w6: R81.1@3918.31,3000 3956.18,3000 3964.1,3007.92 3964.1,3158.8 3988.09,3182.79 3988.09,3274.48 v1(4001.37,3287.76)
  Bottom w6: v1(4001.37,3287.76) 4017.83,3287.76 4173.09,3443.02 4173.09,3631.6 J5.14@4071.05,3733.64
N638520: J5.11 R79.1 | length 1551
  Top w6: R79.1@4434.05,2559.06 4434.05,2556.27 v1(4457.48,2556.27) ; J5.11@4592.7,3733.64 4774.24,3733.64 4811.02,3696.85 4811.02,3610.96 4688.98,3488.91 4688.98,2877.95 v1(4681.1,2870.08)
  Bottom w6: v1(4457.48,2556.27) 4464.75,2556.27 4635.84,2727.36 4635.84,2824.82 v1(4681.1,2870.08)
N1234901: D3.2 R4.2 | length 57
  Top w6: R4.2@146.65,-153.54 150.94,-149.26 150.94,-139.91 179.61,-111.24 D3.2@179.61,-110.24
N5679088: C92.2 L1.1 U2.6 | length 235.9
  Top w20: C92.2@489.17,169.29 489.17,202.66 v1(489.73,202.66)
  Bottom w20: v1(489.73,202.66) 489.73,1.23 v1(490.11,0.85)
N5679096: C92.1 U2.1 | length 59.5
  Top w20: U2.1@454.72,110.24 454.72,168.31 C92.1@455.71,169.29
N5679154: C93.2 R2.2 R159.1 U2.3 | length 138.2
  Top w10: C93.2@378.94,248.03 379.92,247.05 379.92,208.66 U2.3@379.92,110.24
N5680029: F1.1 J1.1
N16925291: D46.1 L4.2 U13.1
N17131711: D86.2 R28.1 | length 500.5
  Top w6: D86.2@4625.98,564.86 4666.35,524.5 v1(4784.32,524.5) ; v1(4762.93,805.05) 4764.55,811.02 R28.1@4786.42,811.02
  Bottom w6: v1(4762.93,805.05) 4766.73,808.85 4784.56,791.01 4784.56,524.5 v1(4784.32,524.5)
N17174872: CON2.42 R101.1 | length 446.9
  Top w6: CON2.42@1192.92,777.62 1192.92,838.85 1204.46,850.39 R101.1@1573.82,850.39
N17174874: D53.2 R101.2 | length 64.8
  Top w6: R101.2@1607.28,850.39 1607.28,832.17 D53.2@1640.24,799.21
N17175777: Q3.3 R43.2 R45.1 U4.2 U4.3 | length 474.8
  Top w20: Q3.3@3850.39,493.76 3980,493.76 ; U4.3@3990.75,565.76 3990.75,505.76 ; R45.1@4078.74,640.75 R43.2@4039.37,640.75 4039.37,565.76 U4.2@4040.75,565.76 4040.75,507.88 4026.63,493.76 4002.75,493.76 ; 3980,493.76 3990.75,504.5 ; 3980,493.76 3988.69,493.76 ; 3988.69,493.76 3990.75,495.81 3990.75,504.5 ; 3988.69,493.76 4002.75,493.76 ; 3990.75,504.5 3990.75,505.76 ; 3990.75,505.76 4002.75,493.76
N17175783: D54.2 U4.1 | length 508.3
  Top w6: D54.2@3748.03,412.76 3748.03,382.81 3752.88,377.95 3834.65,377.95 3850.39,393.7 3850.39,433.07 3870.08,452.76 3927.43,452.76 3948.82,474.15 4055.12,474.15 4090.75,509.78 U4.1@4090.75,565.76
N17177143: C191.2 L2.1 U12.6 | length 223.3
  Top w20: v1(882.54,200.99) 882.87,200.99 C191.2@882.87,169.29
  Bottom w20: v1(876.52,13.74) 874.69,15.57 874.69,193.14 v1(882.54,200.99)
N17177153: C192.2 R173.2 R174.1 U12.3 | length 134.3
  Top w10: C192.2@772.64,248.03 773.62,247.05 773.62,208.66 U12.3@773.62,114.17
N17255318: Q4.1 R51.2 | length 52
  Top w6: Q4.1@112.11,1752.34 113.19,1751.26 R51.2@113.19,1700.79
N17255336: D93.1 J7.2 Q4.3 | length 533
  Top w15: J7.2@-174.41,1807.09 124.35,1807.09 Q4.3@149.61,1832.34 203.45,1832.34 219.48,1816.31 219.48,1757.64 257.28,1719.84 D93.1@263.78,1719.84
  Top w20: Q4.3@149.61,1828.92 Q4.3@149.61,1832.34
N17680063: L5.1 U28.3
N17680065: C7.2 R266.1 R267.2 U28.5 | length 124.4
  Top w10: C7.2@3062.01,2834.65 R267.2@3062.01,2874.02 R266.1@3062.01,2913.39 3062.01,2957.68 U28.5@3062.99,2958.66
N17819196: CA25.1 UA1.16 UA1.20 | length 218.9
  Top w6: CA25.1@2130.32,3031.5 2154.31,3031.5 2196.66,3073.84 UA1.20@2221.65,3073.84 2242.82,3073.84 2248.34,3079.36 2248.34,3131.48 2242.98,3136.84 UA1.16@2221.65,3136.84
N17819206: CA26.1 UA1.23 | length 92.4
  Top w6: CA26.1@2240.16,2969.49 2282.67,3012 UA1.23@2282.67,3044.32
N17819214: CA26.2 UA1.21 | length 142.4
  Top w6: v1(2221.34,2994.26) 2220.2,2994.26 2220.2,2955.98 CA26.2@2240.16,2936.02 ; v1(2233.65,3038.44) 2251.18,3038.47 UA1.21@2251.18,3044.32
  Bottom w6: v1(2221.34,2994.26) 2220.76,2994.84 2230.88,3004.96 2230.88,3038.44 v1(2233.65,3038.44)
N17819230: CA23.1 UA1.34 | length 112.7
  Top w6: UA1.34@2422.44,3121.09 2459.16,3121.09 2491.75,3088.5 2491.75,3081.2 2495.99,3076.96 2510.83,3076.96 CA23.1@2510.83,3078.74
N17819689: CA3.2 CA6.2 CA7.1 RA7.2 RA100.2 | length 266.8
  Top w6: RA7.2@2374.02,3546.26 RA100.2@2413.39,3546.26 2406.5,3539.37 CA3.2@2406.5,3503.94 2406.5,3503.45 v1(2428.61,3503.45) 2451.77,3503.45 CA7.1@2451.77,3503.94 ; v1(2512.57,3439.23) CA6.2@2530.51,3421.26
  Bottom w6: v1(2428.61,3503.45) 2448.34,3503.45 v1(2512.57,3439.23)
N17819691: CA7.2 CA9.2 CA12.1 RA11.2 RA101.2 | length 169.2
  Top w6: RA101.2@2452.76,3546.26 CA12.1@2492.13,3546.26 2485.24,3539.37 CA7.2@2485.24,3503.94 RA11.2@2485.24,3464.57 CA9.2@2530.51,3464.57
N17819723: CA8.2 RA11.1 RA13.1 | length 294.3
  Top w6: CA8.2@2314.96,3456.3 2338.94,3432.32 2338.94,3395.16 2361.79,3372.31 2448.81,3372.31 2459.16,3382.66 2459.16,3425.2 RA13.1@2451.77,3425.2 RA11.1@2451.77,3464.57
N17819725: CA8.1 RA5.1 RA7.1 | length 186.6
  Top w6: RA5.1@2373.03,3464.57 2367.18,3470.42 2356.74,3470.42 CA8.1@2314.96,3512.2 2314.96,3549.37 2345.32,3579.72 RA7.1@2374.02,3579.72
N17838408: C181.2 R195.1 | length 45.3
  Top w6: C181.2@1051.18,3095.47 R195.1@1051.18,3140.75
N17838410: C182.2 R196.1 | length 45.3
  Top w6: C182.2@1007.87,3095.47 R196.1@1007.87,3140.75
N17838457: C88.1 D17.2 J36.3 R25.1 R157.2 | length 523.6
  Top w6: R25.1@1094.49,3306.1 1094.49,3306.4 v1(1116.09,3306.4) 1137.8,3306.4 R157.2@1137.8,3306.1 ; C88.1@1311.02,3260.83 1311.02,3264.11 v1(1288.32,3264.11) 1288.32,3316.86 1311.02,3339.56 D17.2@1311.02,3340.83 1311.02,3472.44 J36.3@1338.58,3472.44
  Bottom w6: v1(1116.09,3306.4) 1277.83,3306.4 1288.32,3295.91 v1(1288.32,3264.11)
N17838500: C89.1 D19.2 J36.4 | length 454.3
  Top w6: J36.4@1338.58,3641.34 1360.86,3641.34 1406.64,3595.56 1406.64,3428.79 1366.14,3388.3 D19.2@1366.14,3340.83 1366.14,3339.56 1347.14,3320.56 1347.14,3279.83 C89.1@1366.14,3260.83
N17838683: D18.2 R20.2 R23.2 R157.1 | length 132.5
  Top w6: R157.1@1137.8,3339.57 1181.1,3339.57 D18.2@1181.1,3340.83 1224.41,3340.83 R20.2@1224.41,3339.57 R23.2@1267.72,3339.57
N17845378: C111.2 R191.2 R193.2 | length 88.6
  Top w15: R193.2@1732.28,3103.35 R191.2@1771.65,3103.35 C111.2@1771.65,3152.56
N17845396: C72.2 R192.2 R194.2 | length 88.6
  Top w15: C72.2@1818.9,3152.56 R194.2@1818.9,3103.35 R192.2@1858.27,3103.35
N17845478: C111.1 U6.3 | length 72
  Top w15: U6.3@1769.4,3255.79 1769.4,3186.02 C111.1@1771.65,3186.02
N17845505: C72.1 R181.1 U6.4 | length 190.4
  Top w15: C72.1@1818.9,3186.02 1819.4,3186.02 U6.4@1819.4,3255.79 1819.4,3298.73 R181.1@1874.02,3353.35
N17845570: C69.1 U6.2 | length 70.8
  Top w15: U6.2@1719.4,3255.79 1719.4,3186.02 C69.1@1720.47,3186.02
N17874598: CA83.2 CA84.1 CA86.1 RA61.1 RA62.2 | length 163.6
  Top w6: RA62.2@1993.11,3503.94 2031.5,3503.94 CA86.1@2031.5,3504.92 2066.93,3504.92 RA61.1@2066.93,3510.83 CA83.2@2106.3,3510.83 2109.25,3507.87 CA84.1@2148.62,3507.87
N17874616: CA86.2 CA87.1 CA89.1 RA63.2 RA65.2 | length 165.6
  Top w6: RA63.2@1993.11,3468.5 2031.5,3468.5 CA86.2@2031.5,3471.46 2066.93,3471.46 RA65.2@2066.93,3465.55 CA89.1@2106.3,3465.55 2109.25,3468.5 CA87.1@2148.62,3468.5
N17874634: CA85.2 RA62.1 | length 41.3
  Top w6: CA85.2@1918.31,3503.94 RA62.1@1959.65,3503.94
N17874636: CA88.2 RA63.1 | length 41.3
  Top w6: CA88.2@1918.31,3468.5 RA63.1@1959.65,3468.5
N17914489: R38.2 R209.1 R210.1 U63.4 | length 144.7
  Top w6: U63.4@4831.69,3486.22 4831.69,3530.51 R38.2@4830.71,3531.5 R210.1@4830.71,3570.87 4830.26,3570.87 4830.26,3586.23 4834.86,3590.83 4844.77,3590.83 R209.1@4864.17,3610.24
N17914651: C53.2 C57.1 D125.1 L7.2 U63.1
N17914681: C53.1 D81.3
N17914691: C231.2 D83.1 R61.1
N17914697: R207.1 R208.1 U63.3 | length 109.6
  Top w10: U63.3@4941.93,3486.22 4941.93,3503.94 4954.72,3516.73 R208.1@4989.17,3516.73 R207.1@5028.54,3516.73
N17914762: C232.1 D81.2 R59.1
N17915278: J39.6 R205.1 R206.2 | length 296.7
  Top w6: R206.2@5139.76,2606.3 R205.1@5139.76,2566.93 5139.76,2566.53 5163.15,2566.53 v1(5163.15,2567) ; J39.6@5228.35,2496.06 5284.56,2496.06 v1(5297.68,2509.18)
  Bottom w6: v1(5163.15,2567) 5168.53,2566.53 5234.31,2566.53 5291.66,2509.18 v1(5297.68,2509.18)
N17963617: RU1.2 U3.3 | length 51.3
  Top w6: RU1.2@566.93,3300.2 611.22,3300.2 U3.3@616.14,3295.28
N17967381: C220.1 Q8.3 RU6.1 U14.10 | length 305.5
  Top w6: C220.1@644.69,2133.86 644.69,2120.89 651.38,2114.2 669.29,2114.2 678.15,2105.34 RU6.1@678.15,2090.55 746.4,2090.55 Q8.3@754.28,2098.43
  Top w12: U14.10@566.93,2041.73 566.93,2114.38 586.41,2133.86 C220.1@644.69,2133.86
N17967469: U10.12 X3.1 | length 348.2
  Top w8: X3.1@433.07,1651.57 433.07,1650.08 438.5,1650.08 479.29,1690.87 479.29,1735.56 497.56,1753.83 543.08,1753.83 570.63,1781.38 570.63,1809.58 612.83,1851.77 U10.12@653.54,1851.77
N17967471: U10.11 X3.3 | length 189.1
  Top w8: X3.3@527.56,1718.5 584.63,1775.58 584.63,1803.78 611.76,1830.91 U10.11@653.54,1830.91
N17967477: C173.1 U10.10 | length 113.2
  Top w6: C173.1@598.43,1737.2 598.43,1784.8 623.66,1810.04 U10.10@653.54,1810.04
N17967572: D173.2 U11.8 | length 87.4
  Top w6: U11.8@942.91,1897.64 994.07,1897.64 1015.12,1876.59 D173.2@1015.12,1870.08
N18042692: C143.1 U64.136 | length 1581.3
  Top w6: C143.1@422.24,2326.77 434.46,2338.99 1704.24,2338.99 1847.94,2482.69 1911.01,2482.69 1925.19,2468.5 U64.136@1933.07,2468.5
N18042694: C144.1 U64.135 | length 1581.3
  Top w6: C144.1@422.24,2362.2 434.46,2349.99 1699.63,2349.99 1843.33,2493.69 1911.01,2493.69 1925.19,2507.87 U64.135@1933.07,2507.87
N18042720: C139.1 U64.138 | length 1581.3
  Top w6: C139.1@422.24,2248.03 434.46,2260.25 1743.45,2260.25 1887.15,2403.95 1911.01,2403.95 1925.19,2389.76 U64.138@1933.07,2389.76
N18042722: C140.1 U64.137 | length 1581.3
  Top w6: C140.1@422.24,2283.46 434.46,2271.25 1735.83,2271.25 1879.53,2414.95 1911.01,2414.95 1925.19,2429.13 U64.137@1933.07,2429.13
N18042768: R65.1 U64.142 | length 1689.3
  Top w6: R65.1@422.24,2133.86 430.07,2126.03 452.68,2126.03 534.63,2207.99 1828.69,2207.99 1912.03,2291.33 1952.65,2291.33 1960.7,2283.28 1960.7,2237.03 1955.95,2232.28 U64.142@1933.07,2232.28
N18042770: R69.1 U64.141 | length 1580.9
  Top w6: R69.1@422.24,2102.36 434.88,2115 457.44,2115 539.26,2196.82 1833.08,2196.82 1907.91,2271.65 U64.141@1933.07,2271.65
N18042772: R76.1 U64.140 | length 1578
  Top w6: R76.1@422.24,2177.17 432.49,2187.41 459.22,2187.41 496.31,2224.51 1780.01,2224.51 1880.71,2325.21 1911.01,2325.21 1925.19,2311.02 U64.140@1933.07,2311.02
N18042774: R77.1 U64.139 | length 1578
  Top w6: R77.1@422.24,2208.66 432.49,2198.41 454.66,2198.41 491.75,2235.51 1774.98,2235.51 1875.68,2336.21 1911.01,2336.21 1925.19,2350.39 U64.139@1933.07,2350.39
N18042804: C141.1 U64.144 | length 1699.5
  Top w6: C141.1@422.24,2062.99 434.46,2050.78 444.82,2050.78 574.72,2180.68 1880.83,2180.68 1912.78,2212.63 1957.1,2212.63 1965.15,2204.58 1965.15,2156.88 1961.81,2153.54 U64.144@1933.07,2153.54
N18042806: C142.1 U64.143 | length 1579.3
  Top w6: C142.1@422.24,2027.56 434.46,2039.78 449.42,2039.78 579.31,2169.67 1888.29,2169.67 1911.53,2192.91 U64.143@1933.07,2192.91
N171758202: Q3.1 R47.1 | length 178.5
  Top w6: Q3.1@3812.89,413.76 3807.09,413.76 3807.09,506.18 3832.41,531.5 3843.5,531.5 R47.1@3867.13,555.12
N171758280: C37.2 R43.1 | length 39.4
  Top w20: C37.2@4000,674.21 R43.1@4039.37,674.21
N171771995: C191.1 U12.1 | length 55.5
  Top w20: U12.1@848.43,114.17 849.41,115.16 C191.1@849.41,169.29
N179147341: C57.2 D83.3
PA-SHDN-PE15: R179.2 U6.1 U64.133 | length 908.9
  Top w6: R179.2@1595.47,3240.16 U6.1@1669.4,3240.16 ; U6.1@1669.4,3255.79 U6.1@1669.4,3240.16 ; v1(1838.93,2949.92) 1794.63,2949.92 1669.4,3075.15 U6.1@1669.4,3240.16 ; v1(1882.17,2668.94) 1882.17,2598.24 1893.79,2586.61 U64.133@1933.07,2586.61
  Bottom w6: v1(1838.93,2949.92) 1838.93,2945.43 1860,2924.36 1860,2678.14 1869.2,2668.94 v1(1882.17,2668.94)
PA-VDD: C70.1 C197.1 FB1.1 U6.6 | length 457.7
  Top w25: C70.1@1595.47,3334.65 1595.47,3391.24 1601.36,3397.13 FB1.1@1601.36,3459.63 1601.36,3507 1601.28,3507.08 1601.28,3549.7 v1(1601.73,3560.04) ; v1(1741.35,3559.7) 1740.72,3549.82 1769.4,3521.14 U6.6@1769.4,3481.79
  Bottom w25: v1(1601.73,3560.04) 1741.35,3560.04 v1(1741.35,3559.7)
PHYRSTB: CE19.2 RE18.2 U15.12 U64.99 | length 923.9
  Top w6: U64.99@3271.65,2704.73 3271.65,2753.62 3287.92,2769.89 3543.42,2769.89 3612.26,2701.04 3796.48,2701.04 3824.56,2729.12 3912.41,2729.12 ; RE18.2@3918.31,2751.97 3918.31,2734.87 ; U15.12@4025.59,2744.09 3976.85,2744.09 3941.42,2708.66 CE19.2@3918.31,2708.66 3918.31,2723.22 ; 3912.41,2729.12 3913.24,2729.12 ; 3912.41,2729.12 3918.31,2723.22 ; 3913.24,2729.12 3918.31,2729.12 ; 3913.24,2729.12 3913.24,2729.8 3918.31,2734.87 ; 3918.31,2723.22 3918.31,2729.12 ; 3918.31,2729.12 3918.31,2734.87
PM5-BEEP: R51.1 U64.169 | length 2240.3
  Top w6: v1(145.32,1474.24) 157.32,1486.24 225.08,1486.24 355.43,1355.88 1615.27,1355.88 1651.39,1392 1803.62,1392 1901.1,1294.53 1901.1,1193.39 1925.19,1169.29 U64.169@1933.07,1169.29 ; v1(145.32,1522.24) 145.32,1699.46 R51.1@146.65,1700.79
  Bottom w6: v1(145.32,1474.24) v1(145.32,1522.24)
PWRON: C3.1 D4.2 K2.2 U64.168 | length 4543.2
  Top w6: U64.168@1933.07,1208.66 1957.72,1208.66 1978.01,1228.96 2078.09,1228.96 v1(2078.09,1227.99) ; v1(2072.25,595.6) 2072.25,595.03 2108.88,595.03 2291.46,412.45 3462.14,412.45 3810.83,63.76 3810.83,-142.77 3860.64,-192.57 4349.81,-192.57 4373.21,-169.17 4373.21,90.43 4429.35,146.57 4838.67,146.57 C3.1@4886.81,98.43 D4.2@4930.82,98.43 4930.82,18 K2.2@4937.01,11.81
  Bottom w6: v1(2072.25,595.6) 2117.77,641.12 2117.77,1210.66 2100.44,1227.99 v1(2078.09,1227.99)
REGOUT: L3.1 U15.30
RGMII0-CLK-25M: R109.1 U64.82 | length 1269.3
  Top w8: U64.82@3507.87,2153.54 3537.01,2153.54 3698.23,2314.76 4154.97,2314.76 4230.59,2390.38 v1(4250.14,2390.38) ; v1(4290.61,2759.66) 4290.61,2759.84 R109.1@4317.91,2759.84
  Bottom w8: v1(4250.14,2390.38) 4249.36,2388.94 4245.72,2390.92 4235.63,2401.01 4235.63,2633.32 4290.61,2688.3 v1(4290.61,2759.66)
RGMII0-CLKIN-125M: RE15.1 U64.83 | length 1175.7
  Top w8: U64.83@3507.87,2192.91 3536.48,2192.91 3672.33,2328.76 4149.1,2328.76 4237.97,2417.63 v1(4256.67,2417.63) ; v1(4288.59,2656.54) 4297.57,2665.52 4328.28,2665.52 4338.23,2675.47 4338.23,2675.83 RE15.1@4351.38,2688.98
  Bottom w8: v1(4256.67,2417.63) 4256.24,2417.2 4251.37,2422.07 4251.37,2619.32 v1(4288.59,2656.54)
RGMII0-MDC: U15.13 U64.98 | length 808.3
  Top w6: U64.98@3311.02,2704.73 3311.02,2751.06 3317.62,2757.66 3538.68,2757.66 3607.29,2689.04 3946.87,2689.04 3986.18,2728.35 U15.13@4025.59,2728.35
RGMII0-MDIO: RE21.2 U15.14 U64.97 | length 784.9
  Top w6: U64.97@3350.39,2704.73 3350.39,2741.82 3354.18,2745.61 3533.76,2745.61 3602.32,2677.04 3908.75,2677.04 3918.31,2667.48 RE21.2@3918.31,2653.54 3935.85,2652.94 3995.5,2712.6 U15.14@4025.59,2712.6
